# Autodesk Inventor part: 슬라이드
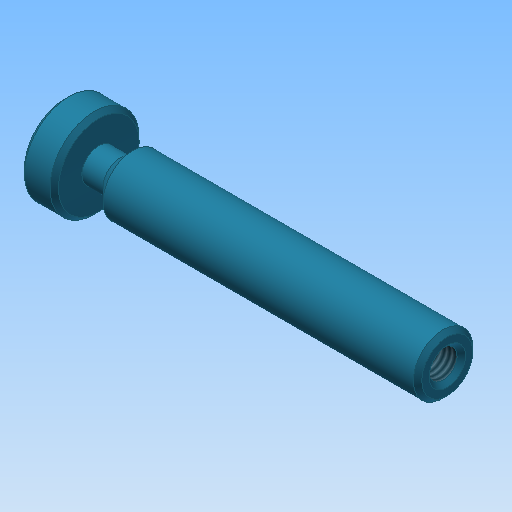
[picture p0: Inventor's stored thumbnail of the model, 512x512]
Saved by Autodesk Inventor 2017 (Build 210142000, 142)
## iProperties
Created: 2015-12
Part Number: 슬라이드
Document SubType Name: Modeling
Designer: mdu
Density: 8.08 g/cm^3
Material: 스테인리스강
Mass: 114.493 g
Surface Area: 49.8963 cm^2
Volume: 14.17 cm^3
Appearance: 터키옥색
Author: mdu
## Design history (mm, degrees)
sketch "스케치1"
  geometry: L1 (-45, 0)-(45, 0); L2 (-45, 0)-(-45, 10.5); L3 (-45, 10.5)-(-37, 10.5); L4 (-37, 10.5)-(-37, 4); L5 (-37, 4)-(-32, 4); L6 (-32, 4)-(-29, 7); L7 (-29, 7)-(45, 7); L8 (45, 7)-(45, 0); 2 further points
  constraints: 16 end point, 4 parallel, 2 perpendicular, 1 coincident, 1 horizontal, 1 midpoint
  dimensions: "d0" = 90 distance of L1.start L1.end; "d1" = 21 diameter of L3 L1; "d2" = 14 diameter of L7 L1; "d3" = 8 diameter of L5 L1; "d4" = 8 distance of L2.end L3.end; "d5" = 5 distance of L4.end L5.end; "d6" = 135 deg angle of L6 L5
revolve "회전1" sketch "스케치1" stored, may be unused: angle "d7" = 90 deg
chamfer "모따기1" distance "d8" = 1; stored, may be unused: second distance "d9" = 2, angle "d10" = 45 deg
hole "구멍1" diameter "d13" = 6.647; stored, may be unused: countersink angle "d17" = 90 deg, drill point angle "d19" = 118 deg; dims "d11" = 10, "d12" = 10, "d14" = 9, "d15" = 4, "d16" = 2, "d18" = 12
chamfer "모따기2" distance "d20" = 1; stored, may be unused: second distance "d21" = 2, angle "d22" = 45 deg
node "솔리드1"
